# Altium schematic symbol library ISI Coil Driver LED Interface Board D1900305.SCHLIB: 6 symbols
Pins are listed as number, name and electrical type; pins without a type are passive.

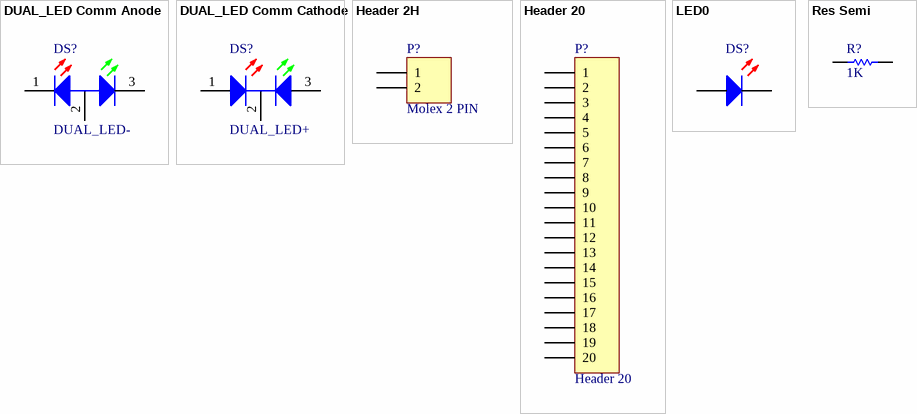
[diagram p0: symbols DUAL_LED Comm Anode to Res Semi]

## DUAL_LED Comm Anode
designator DS?, comment DUAL_LED-
Green, Red  LED Indication - Discrete 2.2V Green, 2V Red Radial - 3 Leads; Manufacturer: Lumex; Manufacturer Part Number: SSL-LX3059IGW-CA; Description: LED Bi-Color Green/Red 565nm/635nm 3-Pin T-1; Forward Current: 20mA; Luminous Intensity: 30mcd; Lens Style: Dome,Diffused,Colorless; Viewing Angle: 60°; Wavelength: 635nm; Number of LEDs: 2
footprint LED R/G Comm Anode (+)
pins: 1 A, 2 K, 3 A

## DUAL_LED Comm Cathode
designator DS?, comment DUAL_LED+
Green, Red  LED Indication - Discrete 2.2V Green, 2V Red Radial - 3 Leads; Manufacturer: Lumex; Manufacturer Part Number: SSL-LX3059IGW; Lens Color: White; Viewing Angle: 60°; Test Current: 20mA; Lens Style: Dome,Round,Diffused,Colorless; Luminous Intensity: 30mcd; Lens Transparency: Diffused; Dominant Wavelength: 635nm; Forward Current: 150mA; Power Dissipation: 105mW; Wavelength: 565nm; Number of LEDs: 2
footprint LED R/G COMM CATHODE (-)
pins: 1 A, 2 K, 3 A

## Header 2H
designator P?, comment Molex 2 PIN
Header, 2-Pin, Right Angle; Number of Positions: 2; Gender: Male; Contact Resistance: 10mR; Current Rating: 4A; Voltage Rating: 250V; Max Current Rating: 7A; Insulation Resistance: 50GR; Pitch: 2.54mm; Approvals: UL,CSA
signal-integrity model Connector
footprint 2Pin_Molex 100 mil
pins: 1, 2

## Header 20
designator P?
Header, 20-Pin; Manufacturer: Amphenol FCI; Manufacturer Part Number: 71918-120LF; Current Rating: 1A; Mating Cycles: 250; Number of Poles: 20; Voltage Rating: 1.5kV; Insulation Resistance: 100GR; Gender: Male; Connector Type: Male Pin; Pitch: 2.54mm; Contact Post Length: 2.9mm; Row Spacing: 0.1inch; Hole Diameter: 1mm; Approvals: UL,CSA
signal-integrity model Connector
footprint IDC 20 _Vertical
pins: 1, 2, 3, 4, 5, 6, 7, 8, 9, 10, 11, 12, 13, 14, 15, 16, 17, 18, 19, 20

## LED0
designator DS?  (value not drawn)
Red 640nm LED Indication - Discrete 1.85V Radial; Manufacturer: Kingbright; Manufacturer Part Number: WP710A10SRD/F; Lens Style: Dome,Diffused; Viewing Angle: 40°; Luminous Intensity: 160mcd; Test Current: 20mA; Lens Transparency: Diffused
simulation model LED0 (Diode)
footprint RED_led
pins: 1 A, 2 K

## Res Semi
designator R?, comment 1K
Semiconductor Resistor; Manufacturer: Panasonic; Manufacturer Part Number: ERJ-8ENF1001V; Resistance: 1kR; Tolerance: 1%; Voltage Rating: 200V; Power Rating: 250mW; Temperature Coefficient: 100ppm/°C
simulation model RES (Semiconductor Resistor)
signal-integrity model Res Semi
pins: 1, 2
